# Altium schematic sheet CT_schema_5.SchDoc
size 410 x 272 mm
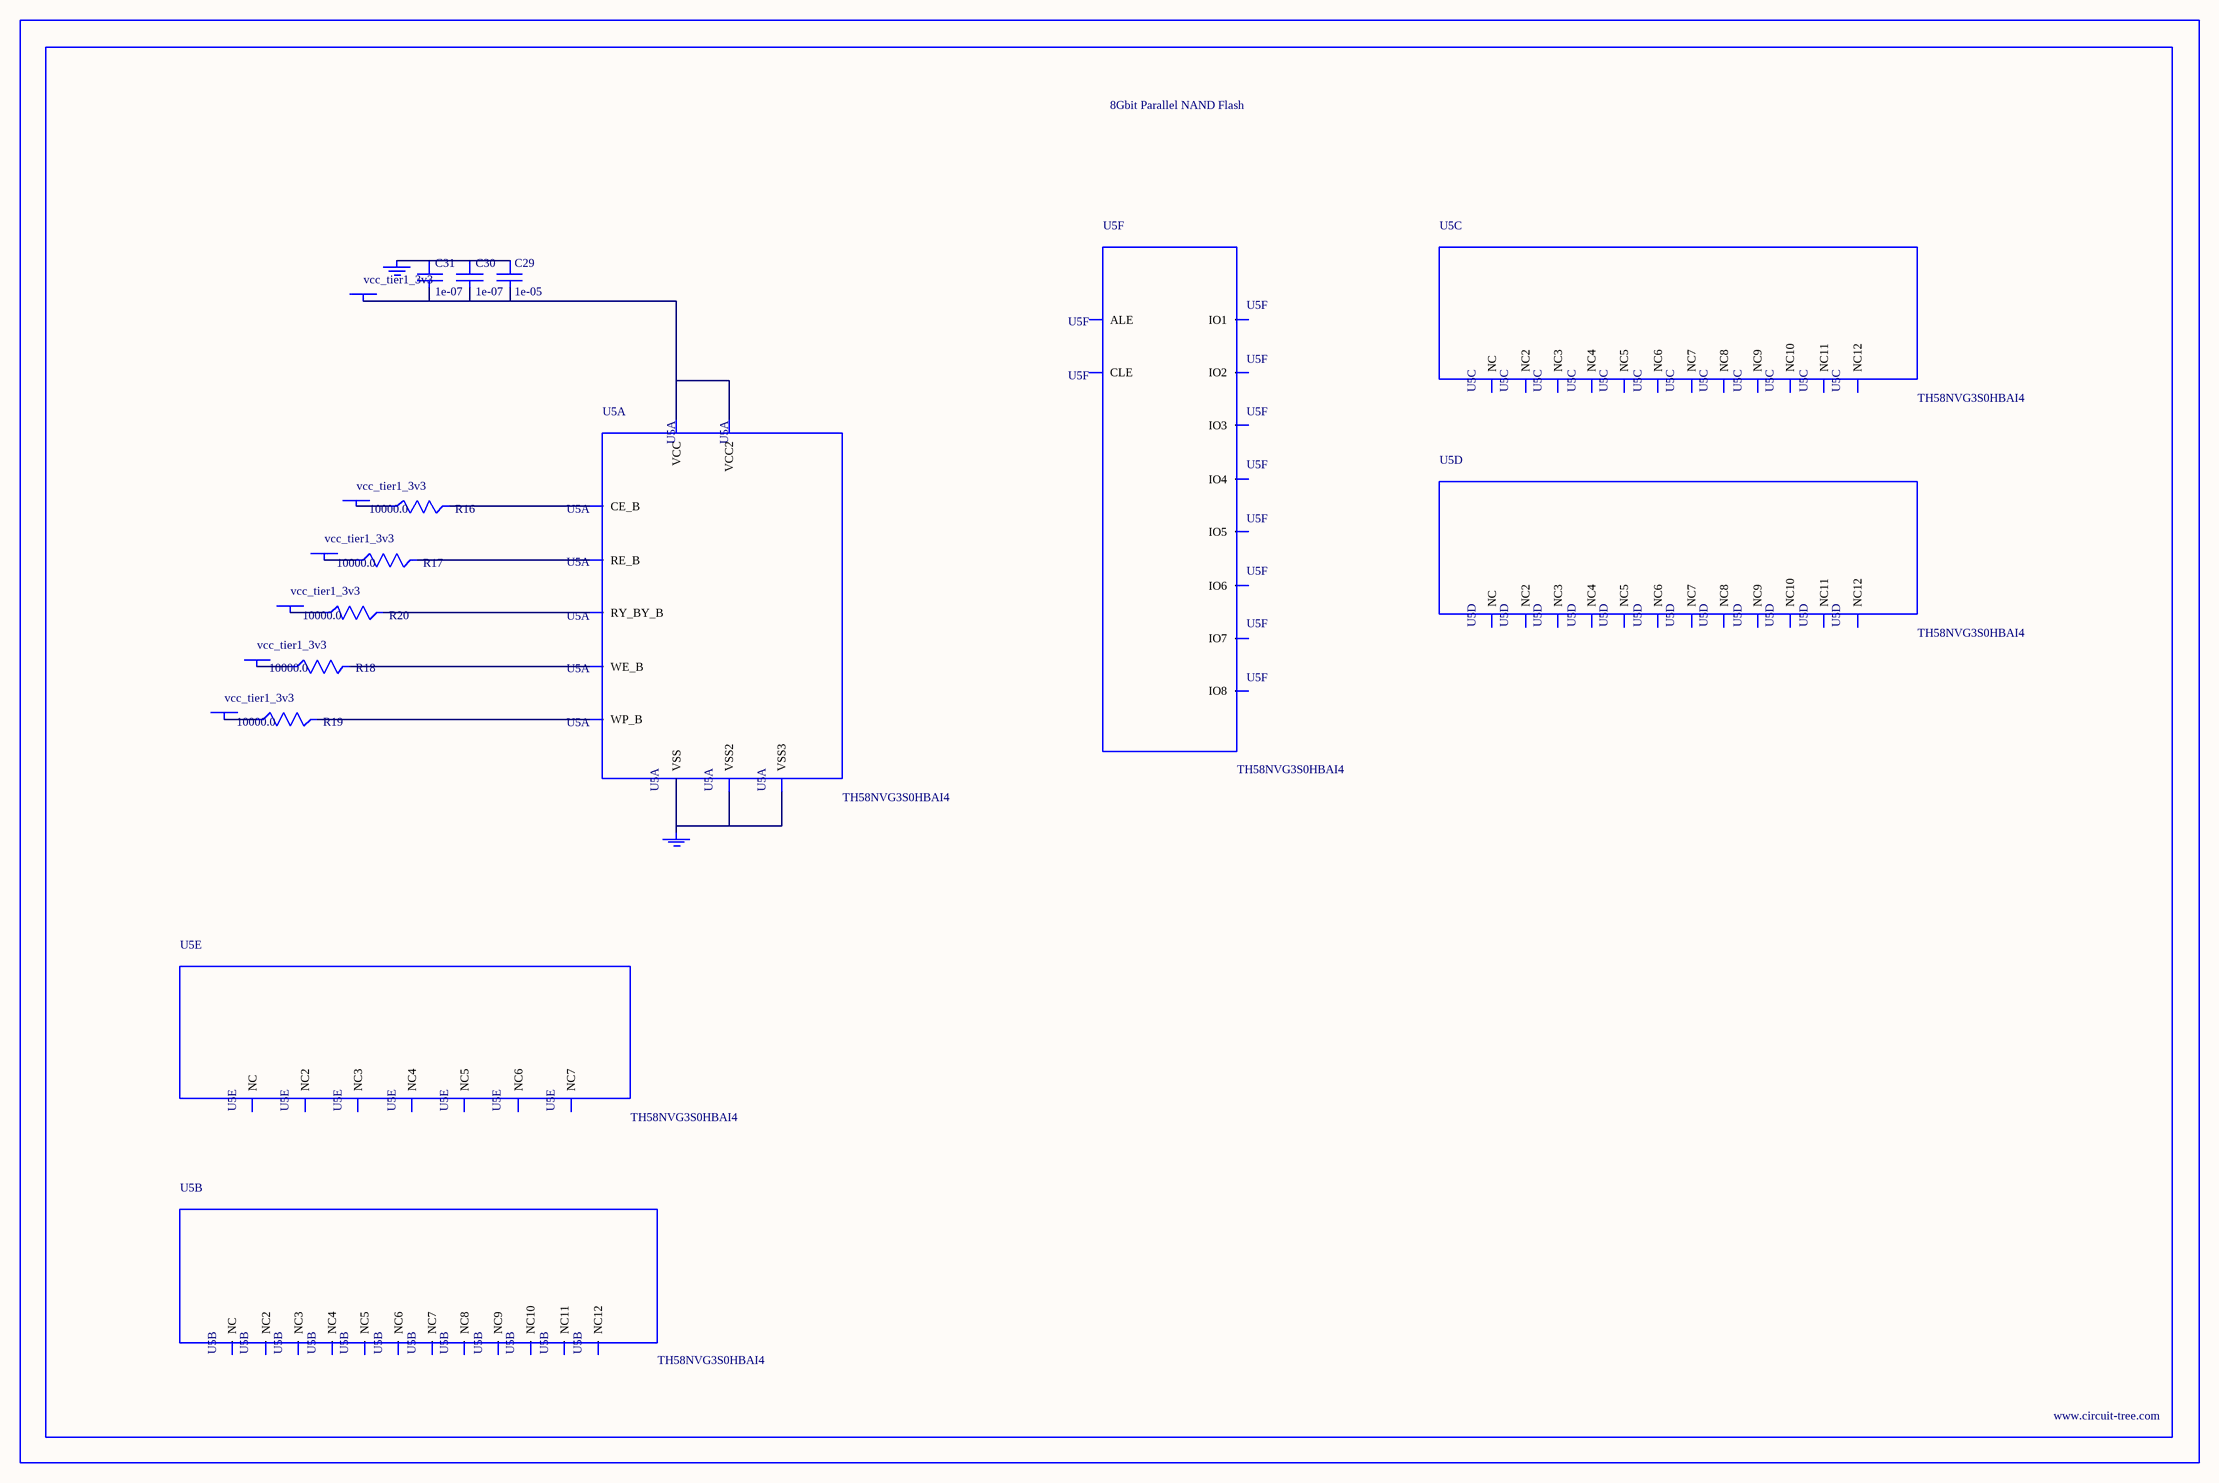
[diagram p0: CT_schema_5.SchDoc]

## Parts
BORDER4  (no value)
C29  1e-05  [C0805]
C30  1e-07  [C0402]
C31  1e-07  [C0402]
GND_INSTANCE_4_0  (no value)
GND_INSTANCE_4_1  (no value)
POWER_INSTANCE_4_0  vcc_tier1_3v3
POWER_INSTANCE_4_1  vcc_tier1_3v3
POWER_INSTANCE_4_2  vcc_tier1_3v3
POWER_INSTANCE_4_3  vcc_tier1_3v3
POWER_INSTANCE_4_4  vcc_tier1_3v3
POWER_INSTANCE_4_5  vcc_tier1_3v3
R16  10000.0  [R0603]
R17  10000.0  [R0603]
R18  10000.0  [R0603]
R19  10000.0  [R0603]
R20  10000.0  [R0603]
U5  TH58NVG3S0HBAI4  [TH58NVG3S0HBAI4]  (parts A,B,C,D,E,F of 6)

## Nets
NetC29_1: C29.1 C30.1 C31.1 GND_INSTANCE_4_0.0(GND)
NetC29_2: C29.2 C30.2 C31.2 POWER_INSTANCE_4_5.0(PWR) U5.H8(VCC) U5.J6(VCC2)
NetGND_INSTANCE_4_1_0: GND_INSTANCE_4_1.0(GND) U5.C5(VSS) U5.K3(VSS2) U5.K8(VSS3)
NetPOWER_INSTANCE_4_0_0: POWER_INSTANCE_4_0.0(PWR) R16.1
NetPOWER_INSTANCE_4_1_0: POWER_INSTANCE_4_1.0(PWR) R17.1
NetPOWER_INSTANCE_4_2_0: POWER_INSTANCE_4_2.0(PWR) R18.1
NetPOWER_INSTANCE_4_3_0: POWER_INSTANCE_4_3.0(PWR) R19.1
NetPOWER_INSTANCE_4_4_0: POWER_INSTANCE_4_4.0(PWR) R20.1
NetR16_2: R16.2 U5.C6(CE_B)
NetR17_2: R17.2 U5.D4(RE_B)
NetR18_2: R18.2 U5.C7(WE_B)
NetR19_2: R19.2 U5.C3(WP_B)
NetR20_2: R20.2 U5.C8(RY_BY_B)

Not connected (* = marked no-connect by the designer): U5 A1(NC) A2(NC3) A9(NC4) A10(NC2) B1(NC5) B9(NC7) B10(NC6) C4(ALE) D3(NC8) D5(CLE) D6(NC9) D7(NC10) D8(NC11) E3(NC12) E4(NC) E5(NC2) E6(NC3) E7(NC4) E8(NC5) F3(NC6) F4(NC7) F5(NC8) F6(NC9) F7(NC10) F8(NC11) G3(NC12) G4(NC) G5(NC2) G6(NC3) G7(NC4) G8(NC5) H3(NC6) H4(IO1) H5(NC7) H6(NC8) H7(NC9) J3(NC10) J4(IO2) J5(NC11) J7(IO6) J8(IO8) K4(IO3) K5(IO4) K6(IO5) K7(IO7) L1(NC12) L2(NC2) L9(NC3) L10(NC) M1(NC4) M2(NC6) M9(NC7) M10(NC5)

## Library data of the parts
BORDER4 = BORDER_PAGE4
C29 = C0805C106K8RACTU
C30 C31 = C0402C104K3RACTU
GND_INSTANCE_4_0 GND_INSTANCE_4_1 = GND
POWER_INSTANCE_4_0-POWER_INSTANCE_4_5 = PWR
R16-R20 = RC0603JR-0710KL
